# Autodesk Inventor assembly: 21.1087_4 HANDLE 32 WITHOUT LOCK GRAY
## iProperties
Created: 2007-03
Part Number: 21.1087_4 HANDLE 32 WITHOUT LOCK GRAY
Document SubType Name: Assembly
Designer: Andy Moles
Translation Standard: STEP AP214IS
File Name: 1000-U366_ASM
Preprocessor: PRO/ENGINEER BY PARAMETRIC TECHNOLOGY CORPORATION, 2003200
Postprocessor: Build: 344b, Release: 11 SP2 - Date: Fri 08/18/2006
Sent Units: MILLIMETERS
Uncertainty: 0.015997586413449998
Author: Andy Moles
